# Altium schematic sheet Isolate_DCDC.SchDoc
size A4
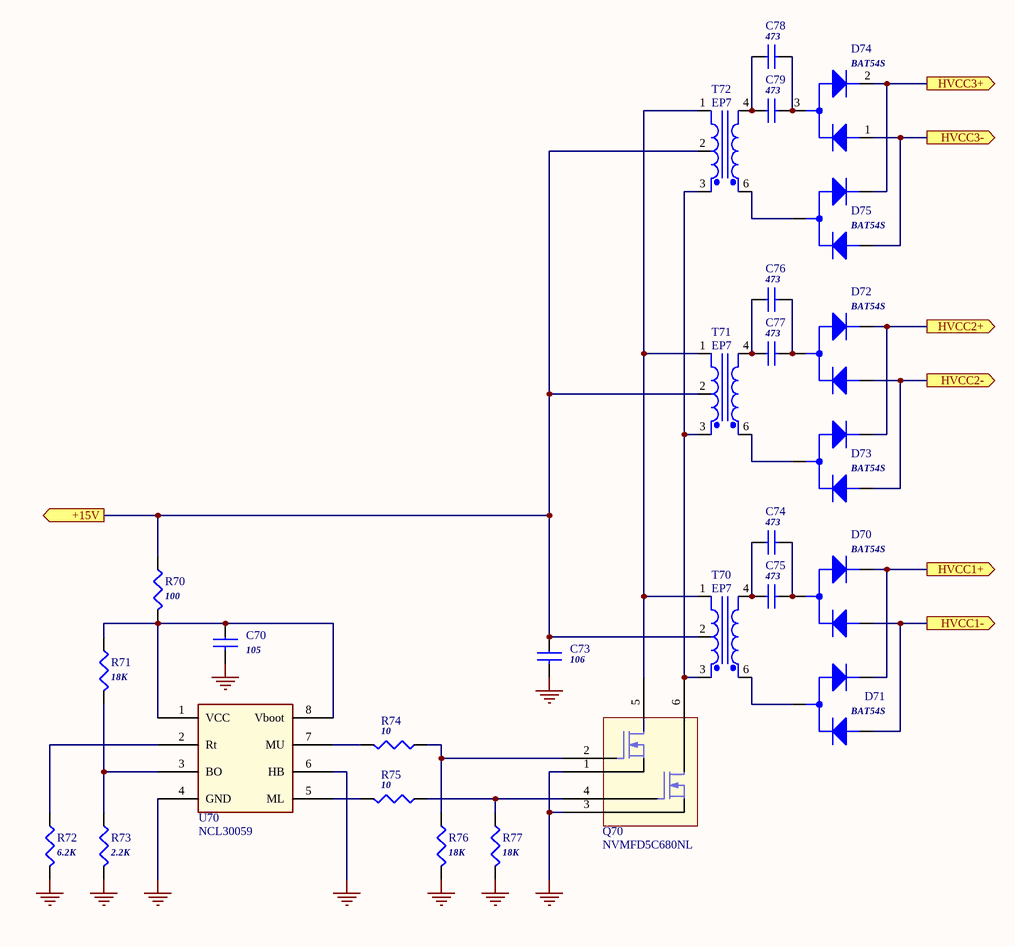
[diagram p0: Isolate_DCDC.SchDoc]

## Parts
C70  105  [SMT_0805_CM]
C73  106  [SMT_1206_CM]
C74  473  [SMT_1206_CM]
C75  473  [SMT_1206_CM]
C76  473  [SMT_1206_CM]
C77  473  [SMT_1206_CM]
C78  473  [SMT_1206_CM]
C79  473  [SMT_1206_CM]
D70  BAT54S  [SOT-23-3L]
D71  BAT54S  [SOT-23-3L]
D72  BAT54S  [SOT-23-3L]
D73  BAT54S  [SOT-23-3L]
D74  BAT54S  [SOT-23-3L]
D75  BAT54S  [SOT-23-3L]
Q70  NVMFD5C680NL  [SO8FL]
R70  100  [SMT_0805_RM]
R71  18K  [SMT_0805_RM]
R72  6.2K  [SMT_0805_RM]
R73  2.2K  [SMT_0805_RM]
R74  10  [SMT_0805_RM]
R75  10  [SMT_0805_RM]
R76  18K  [SMT_0805_RM]
R77  18K  [SMT_0805_RM]
T70  EP7  [EP7_ED8]
T71  EP7  [EP7_ED8]
T72  EP7  [EP7_ED8]
U70  NCL30059  [Sop8]

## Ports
+15V (out), HVCC1+ (out), HVCC1- (out), HVCC2+ (out), HVCC2- (out), HVCC3+ (out), HVCC3- (out)

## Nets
PGND: C70.2 C73.2 Q70.1(S1) Q70.3(S2) R72.2 R73.2 R76.2 R77.2 U70.4(GND) U70.6(HB)
+15V: C73.1 R70.1 T70.2(SecCT) T71.2(SecCT) T72.2(SecCT) ; port +15V
HVCC1+: D70.2 D71.2 ; port HVCC1+
HVCC1-: D70.1 D71.1 ; port HVCC1-
HVCC2+: D72.2 D73.2 ; port HVCC2+
HVCC2-: D72.1 D73.1 ; port HVCC2-
HVCC3+: D74.2 D75.2 ; port HVCC3+
HVCC3-: D74.1 D75.1 ; port HVCC3-
NetC70_1: C70.1 R70.2 R71.1 U70.1(VCC) U70.8(Vboot)
NetC74_1: C74.1 C75.1 T70.4(Pri-)
NetC74_2: C74.2 C75.2 D70.3
NetC76_1: C76.1 C77.1 T71.4(Pri-)
NetC76_2: C76.2 C77.2 D72.3
NetC78_1: C78.1 C79.1 T72.4(Pri-)
NetC78_2: C78.2 C79.2 D74.3
NetD71_3: D71.3 T70.6(Pri+)
NetD73_3: D73.3 T71.6(Pri+)
NetD75_3: D75.3 T72.6(Pri+)
NetQ70_2: Q70.2(G1) R74.1 R76.1
NetQ70_4: Q70.4(G2) R75.1 R77.1
NetQ70_5: Q70.5(D2) T70.1(Sec-) T71.1(Sec-) T72.1(Sec-)
NetQ70_6: Q70.6(D1) T70.3(Sec+) T71.3(Sec+) T72.3(Sec+)
NetR71_2: R71.2 R73.1 U70.3(BO)
NetR72_1: R72.1 U70.2(Rt)
NetR74_2: R74.2 U70.7(MU)
NetR75_2: R75.2 U70.5(ML)

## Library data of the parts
C70 C73-C79 = CAP NP
D70-D75 = BAT54S/SOT
Q70 = MOSFET_DUAL_N
R70-R73 R76 R77 = R
R74 R75 = R: D5: L20
T70-T72 = Trans CT: Center-Tapped Transformer (Coupled Inductor Model)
